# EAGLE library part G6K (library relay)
Low Signal Relay oeiwcsnts1.omron.com/.. D20G6K0100.pdf
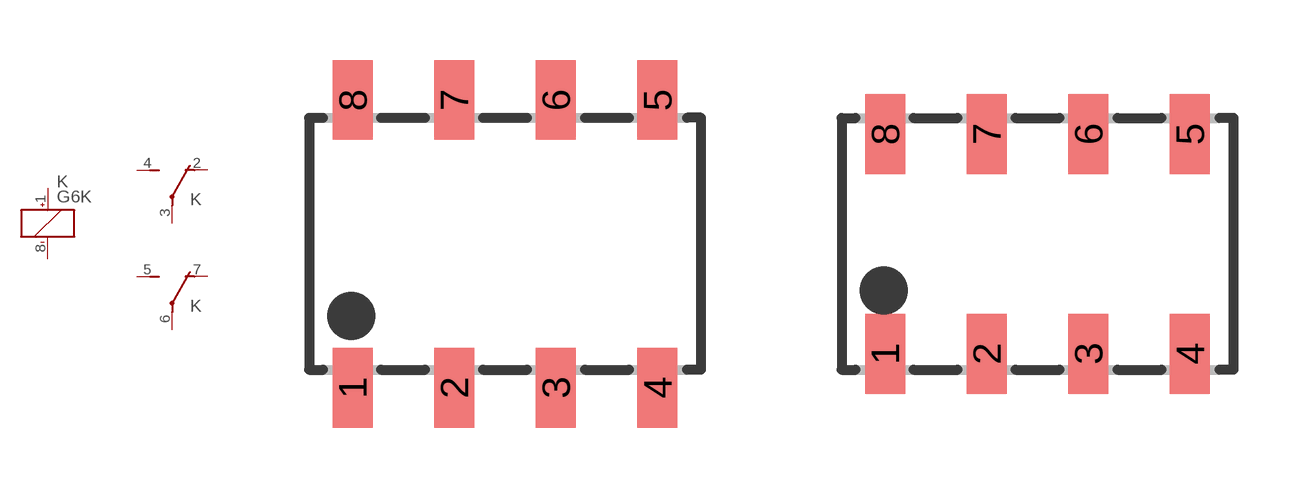
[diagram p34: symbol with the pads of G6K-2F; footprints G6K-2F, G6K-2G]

Designator prefix K; gates 1=K+- 2=U 3=U

## G6K-2F (MF: OMRON COMPONENTS USA; MPN: G6K-2F DC24; OC_FARNELL: 1690427; OC_NEWARK: 36K7467)  [G6K-2F]
1  1:+  pas
2  2:O  pas
3  2:P  pas
4  2:S  pas
5  3:S  pas
6  3:P  pas
7  3:O  pas
8  1:-  pas

## G6K-2G (MF: OMRON COMPONENTS USA; MPN: G6K-2G DC12; OC_FARNELL: 4601695; OC_NEWARK: 93B9118)  [G6K-2G]
Pads as for G6K-2F

## G6K-2P (MF: OMRON COMPONENTS USA; MPN: G6K-2P DC3; OC_FARNELL: 3937276; OC_NEWARK: 89C6482)  [G6K-2P]
Pads as for G6K-2F

## G6K-2F-Y (MF: OMRON COMPONENTS USA; MPN: G6K-2F-Y DC3; OC_FARNELL: 1690316; OC_NEWARK: 89C6451)  [G6K-2F-Y]
Pads as for G6K-2F

## G6K-2G-Y (OC_FARNELL: 4484794; OC_NEWARK: unknown)  [G6K-2G-Y]
Pads as for G6K-2F

## G6K-2P-Y (MF: OMRON COMPONENTS USA; MPN: G6K-2P-Y DC12; OC_FARNELL: 3937276; OC_NEWARK: 34C3464)  [G6K-2P-Y]
Pads as for G6K-2F

## G6KU-2F-Y (MF: OMRON COMPONENTS USA; MPN: G6KU-2F-Y DC3; OC_FARNELL: unknown; OC_NEWARK: 89C6496)  [G6KU-2F-Y]
Pads as for G6K-2F

## G6KU-2G-Y (MF: OMRON COMPONENTS USA; MPN: G6KU-2G-Y DC5; OC_FARNELL: 1690320; OC_NEWARK: 89C6505)  [G6KU-2G-Y]
Pads as for G6K-2F

## G6KU-2P-Y (MF: OMRON COMPONENTS USA; MPN: G6KU-2P-Y DC5; OC_FARNELL: unknown; OC_NEWARK: 35K4536)  [G6KU-2P-Y]
Pads as for G6K-2F

## Footprint G6K-2F (pad centres in mm)
Low Signal Relay oeiwcsnts1.omron.com/.. D20G6K0100.pdf
smd 1 x 2: 1 -3.81,-3.6; 2 -1.27,-3.6; 3 1.27,-3.6; 4 3.81,-3.6; 5 3.81,3.6; 6 1.27,3.6; 7 -1.27,3.6; 8 -3.81,3.6

## Footprint G6K-2G (pad centres in mm)
Low Signal Relay oeiwcsnts1.omron.com/.. D20G6K0100.pdf
smd 1 x 2: 1 -3.81,-2.75; 2 -1.27,-2.75; 3 1.27,-2.75; 4 3.81,-2.75; 5 3.81,2.75; 6 1.27,2.75; 7 -1.27,2.75; 8 -3.81,2.75

## Footprint G6K-2P (pad centres in mm)
Low Signal Relay oeiwcsnts1.omron.com/.. D20G6K0100.pdf
drill 0.8 octagon: 1 -2.54,-2.54; 2 0,-2.54; 3 2.54,-2.54; 4 5.08,-2.54; 5 5.08,2.54; 6 2.54,2.54; 7 0,2.54; 8 -2.54,2.54

## Footprint G6K-2F-Y (pad centres in mm)
Low Signal Relay oeiwcsnts1.omron.com/.. D20G6K0100.pdf
smd 1.2 x 1.8: 1 -3.8,-3.5; 2 -0.6,-3.5; 3 1.6,-3.5; 4 3.8,-3.5; 5 3.8,3.5; 6 1.6,3.5; 7 -0.6,3.5; 8 -3.8,3.5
